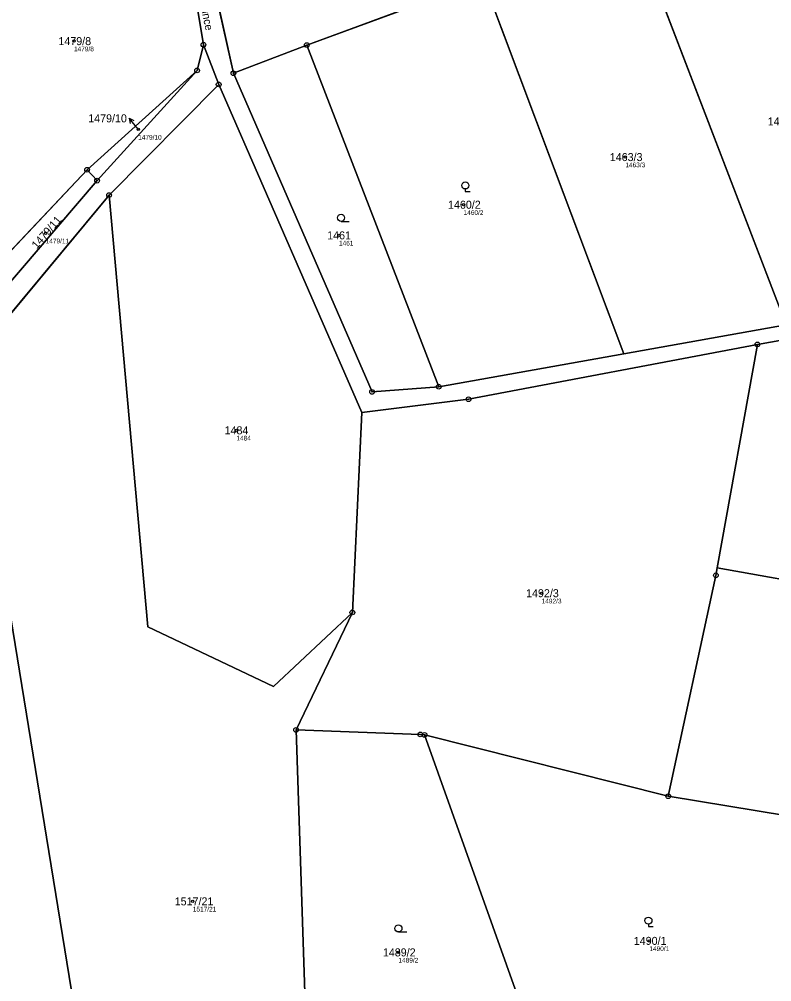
# Model space of a CAD drawing. Extents: x -751550 to -746116, y -1055108 to -1050700.
# Drawn here: x -749262.5 to -749102.6, y -1054841.3 to -1054636.8 of the extents above; entities that cross this region are included whole.
import ezdxf

# ---------------------------------------------------------------- set-up
doc = ezdxf.new("R2010")
doc.units = 0
for name, color, linetype in [('Definiční body', 7, 'Continuous'), ('Hranice parcel', 7, 'Continuous'), ('Parcelní čísla', 7, 'Continuous'), ('Polygon parcely', 7, 'Continuous'), ('Pop  PČ popisy', 7, 'Continuous'), ('Značky bodu BP', 7, 'Continuous'), ('Značky kultur', 7, 'Continuous')]:
    doc.layers.add(name, color=color, linetype=linetype)

msp = doc.modelspace()

# ---------------------------------------------------------------- linework, layer by layer
at = {"layer": 'Definiční body'}
for centre in [(-749250.88, -1054641.46), (-749237.23, -1054660.23), (-749133.7, -1054666.09), (-749168.08, -1054676.21), (-749256.9, -1054682.26), (-749194.56, -1054682.72), (-749216.36, -1054724.13), (-749151.49, -1054758.73), (-749225.63, -1054824.18), (-749128.6, -1054832.57), (-749181.93, -1054835.02)]:
    msp.add_circle(centre, 0.25, dxfattribs=at)
at = {"layer": 'Hranice parcel'}
for p, q in [((-749099.5, -1054701.75), (-749132.12, -1054616.78)), ((-749217, -1054648.29), (-749221.81, -1054626.49)), ((-749163.88, -1054628.48), (-749201.41, -1054642.3)), ((-749134.02, -1054707.89), (-749163.88, -1054628.48)), ((-749223.36, -1054642.22), (-749224.72, -1054647.7)), ((-749220.13, -1054650.67), (-749223.36, -1054642.22)), ((-749201.41, -1054642.3), (-749217, -1054648.29)), ((-749201.41, -1054642.3), (-749173.36, -1054714.89)), ((-749248.08, -1054668.77), (-749224.72, -1054647.7)), ((-749224.72, -1054647.7), (-749245.96, -1054671.1)), ((-749243.42, -1054674.15), (-749220.13, -1054650.67)), ((-749220.13, -1054650.67), (-749189.71, -1054720.33)), ((-749248.08, -1054668.77), (-749268.85, -1054690.77)), ((-749245.96, -1054671.1), (-749248.08, -1054668.77)), ((-749266.39, -1054694.97), (-749245.96, -1054671.1)), ((-749271.75, -1054708.21), (-749243.42, -1054674.15)), ((-749134.02, -1054707.89), (-749099.5, -1054701.75)), ((-749114.17, -1054753.36), (-749105.62, -1054705.87)), ((-749173.36, -1054714.89), (-749134.02, -1054707.89)), ((-749189.71, -1054720.33), (-749191.72, -1054762.81)), ((-749191.72, -1054762.81), (-749203.69, -1054787.76)), ((-749203.69, -1054787.76), (-749201.19, -1054862.86)), ((-749147.34, -1054870.21), (-749176.38, -1054788.81)), ((-749124.6, -1054801.85), (-749176.38, -1054788.81)), ((-749099.27, -1054805.99), (-749124.6, -1054801.85))]:
    msp.add_line(p, q, dxfattribs=at)
for points in [[(-749223.36, -1054642.22), (-749225.67, -1054628.07), (-749237.29, -1054590.37), (-749238.67, -1054580.27)], [(-749217, -1054648.29), (-749187.54, -1054715.98), (-749173.36, -1054714.89)], [(-749191.72, -1054762.81), (-749208.49, -1054778.55), (-749235.21, -1054765.84), (-749243.42, -1054674.15)], [(-749078.57, -1054700.84), (-749088.73, -1054757.9), (-749114.17, -1054753.36)], [(-749078.57, -1054700.84), (-749081.12, -1054701.53), (-749105.62, -1054705.87)], [(-749105.62, -1054705.87), (-749167.02, -1054717.52), (-749189.71, -1054720.33)], [(-749231.96, -1054961.55), (-749235.61, -1054940.24), (-749265.82, -1054754.82), (-749271.75, -1054708.21)], [(-749114.17, -1054753.36), (-749114.46, -1054754.93), (-749124.6, -1054801.85)], [(-749176.38, -1054788.81), (-749177.29, -1054788.71), (-749203.69, -1054787.76)]]:
    msp.add_lwpolyline(points, dxfattribs=at)
at = {"layer": 'Polygon parcely'}
for points in [[(-749106.12, -1054576.37), (-749221.81, -1054626.49), (-749217, -1054648.29), (-749201.41, -1054642.3), (-749163.88, -1054628.48), (-749132.12, -1054616.78), (-749125.24, -1054614.25), (-749102.8, -1054606.42)], [(-749224.72, -1054647.7), (-749223.36, -1054642.22), (-749225.67, -1054628.07), (-749237.29, -1054590.37), (-749238.67, -1054580.27), (-749271.66, -1054630.97), (-749288.04, -1054658.17), (-749278.52, -1054674.25), (-749268.85, -1054690.77), (-749248.08, -1054668.77)], [(-749100.4, -1054605.6), (-749102.8, -1054606.42), (-749125.24, -1054614.25), (-749132.12, -1054616.78), (-749099.5, -1054701.75), (-749081.77, -1054698.59), (-749067.82, -1054694.8)], [(-749099.5, -1054701.75), (-749132.12, -1054616.78), (-749163.88, -1054628.48), (-749134.02, -1054707.89)], [(-749173.36, -1054714.89), (-749134.02, -1054707.89), (-749163.88, -1054628.48), (-749201.41, -1054642.3)], [(-749201.41, -1054642.3), (-749217, -1054648.29), (-749187.54, -1054715.98), (-749173.36, -1054714.89)], [(-749248.08, -1054668.77), (-749245.96, -1054671.1), (-749224.72, -1054647.7)], [(-749220.13, -1054650.67), (-749243.42, -1054674.15), (-749235.21, -1054765.84), (-749208.49, -1054778.55), (-749191.72, -1054762.81), (-749189.71, -1054720.33)], [(-749248.08, -1054668.77), (-749268.85, -1054690.77), (-749266.39, -1054694.97), (-749245.96, -1054671.1)], [(-749231.96, -1054961.55), (-749205.59, -1054950.5), (-749200.41, -1054946.06), (-749200.11, -1054941.77), (-749200, -1054940.27), (-749198.56, -1054939.4), (-749199.43, -1054914.75), (-749199.93, -1054900.6), (-749200.02, -1054897.94), (-749201.19, -1054862.86), (-749203.69, -1054787.76), (-749191.72, -1054762.81), (-749208.49, -1054778.55), (-749235.21, -1054765.84), (-749243.42, -1054674.15), (-749271.75, -1054708.21), (-749265.82, -1054754.82), (-749235.61, -1054940.24)], [(-749088.73, -1054757.9), (-749114.17, -1054753.36), (-749114.46, -1054754.93), (-749124.6, -1054801.85), (-749099.27, -1054805.99), (-749061.12, -1054809.36), (-749041.33, -1054765.13), (-749034.48, -1054742.09), (-749031.21, -1054724.33), (-749028.58, -1054702.31), (-749026.88, -1054677.05), (-749035.13, -1054685.74), (-749050.06, -1054693.14), (-749078.57, -1054700.84)], [(-749078.57, -1054700.84), (-749081.12, -1054701.53), (-749105.62, -1054705.87), (-749114.17, -1054753.36), (-749088.73, -1054757.9)], [(-749167.02, -1054717.52), (-749189.71, -1054720.33), (-749191.72, -1054762.81), (-749203.69, -1054787.76), (-749177.29, -1054788.71), (-749176.38, -1054788.81), (-749124.6, -1054801.85), (-749114.46, -1054754.93), (-749114.17, -1054753.36), (-749105.62, -1054705.87)], [(-749231.09, -1055030.14), (-749229.04, -1055029.57), (-749228.67, -1055030.9), (-749223.27, -1055029.51), (-749220.25, -1055029.63), (-749220.65, -1055027.12), (-749225.44, -1054999.67), (-749231.96, -1054961.55), (-749235.61, -1054940.24), (-749265.82, -1054754.82), (-749271.75, -1054708.21), (-749291.2, -1054720.78), (-749316.97, -1054728.36), (-749323.11, -1054829.31), (-749280.79, -1054962.12), (-749256.6, -1055037.55), (-749254.56, -1055037.58), (-749230.73, -1055031.43)], [(-749143.01, -1054903.27), (-749136.95, -1054899.33), (-749137.45, -1054897.92), (-749147.34, -1054870.21), (-749176.38, -1054788.81), (-749177.29, -1054788.71), (-749203.69, -1054787.76), (-749201.19, -1054862.86), (-749177.86, -1054860.98), (-749158.66, -1054859.44)], [(-749106.18, -1054875.56), (-749088.43, -1054862.87), (-749099.27, -1054805.99), (-749124.6, -1054801.85), (-749176.38, -1054788.81), (-749147.34, -1054870.21), (-749136.29, -1054862.17), (-749121.44, -1054851.51)]]:
    msp.add_lwpolyline(points, close=True, dxfattribs=at)
for points in [[(-749099.5, -1054701.75), (-749134.02, -1054707.89), (-749173.36, -1054714.89), (-749187.54, -1054715.98), (-749217, -1054648.29), (-749221.81, -1054626.49)], [(-749225.67, -1054628.07), (-749223.36, -1054642.22), (-749220.13, -1054650.67), (-749189.71, -1054720.33), (-749167.02, -1054717.52), (-749105.62, -1054705.87), (-749081.12, -1054701.53)], [(-749271.75, -1054708.21), (-749243.42, -1054674.15), (-749220.13, -1054650.67), (-749223.36, -1054642.22), (-749224.72, -1054647.7), (-749245.96, -1054671.1), (-749266.39, -1054694.97)]]:
    msp.add_lwpolyline(points, dxfattribs=at)
at = {"layer": 'Pop  PČ popisy'}
for p, q in [((-749237.27, -1054660.18), (-749239.16, -1054657.85)), ((-749239.16, -1054657.85), (-749238.14, -1054658.31)), ((-749239.16, -1054657.85), (-749238.92, -1054658.94)), ((-749237.23, -1054660.23), (-749237.27, -1054660.18))]:
    msp.add_line(p, q, dxfattribs=at)
at = {"layer": 'Značky bodu BP'}
for centre, radius in [((-749223.36, -1054642.22), 0.5), ((-749223.36, -1054642.22), 0.0303), ((-749201.41, -1054642.3), 0.5), ((-749201.41, -1054642.3), 0.0303), ((-749224.72, -1054647.7), 0.5), ((-749224.72, -1054647.7), 0.0303), ((-749217, -1054648.29), 0.5), ((-749217, -1054648.29), 0.0303), ((-749220.13, -1054650.67), 0.5), ((-749220.13, -1054650.67), 0.0303), ((-749248.08, -1054668.77), 0.5), ((-749248.08, -1054668.77), 0.0303), ((-749245.96, -1054671.1), 0.5), ((-749245.96, -1054671.1), 0.0303), ((-749243.42, -1054674.15), 0.5), ((-749243.42, -1054674.15), 0.0303), ((-749105.62, -1054705.87), 0.5), ((-749105.62, -1054705.87), 0.0303), ((-749173.36, -1054714.89), 0.5), ((-749187.54, -1054715.98), 0.5), ((-749187.54, -1054715.98), 0.0303), ((-749173.36, -1054714.89), 0.0303), ((-749167.02, -1054717.52), 0.5), ((-749167.02, -1054717.52), 0.0303), ((-749114.46, -1054754.93), 0.5), ((-749114.46, -1054754.93), 0.0303), ((-749191.72, -1054762.81), 0.5), ((-749191.72, -1054762.81), 0.0303), ((-749203.69, -1054787.76), 0.5), ((-749203.69, -1054787.76), 0.0303), ((-749177.29, -1054788.71), 0.5), ((-749177.29, -1054788.71), 0.0303), ((-749176.38, -1054788.81), 0.5), ((-749176.38, -1054788.81), 0.0303), ((-749124.6, -1054801.85), 0.5), ((-749124.6, -1054801.85), 0.0303)]:
    msp.add_circle(centre, radius, dxfattribs=at)
at = {"layer": 'Značky kultur'}
for p, q in [((-749167.71, -1054672.87), (-749167.71, -1054673.37)), ((-749167.71, -1054673.37), (-749166.71, -1054673.37)), ((-749194.12, -1054679.74), (-749192.37, -1054679.74)), ((-749128.8, -1054829.02), (-749128.8, -1054829.52)), ((-749181.92, -1054830.68), (-749180.17, -1054830.68)), ((-749128.8, -1054829.52), (-749127.8, -1054829.52))]:
    msp.add_line(p, q, dxfattribs=at)
for centre in [(-749167.71, -1054672.12), (-749194.12, -1054678.99), (-749128.8, -1054828.27), (-749181.92, -1054829.93)]:
    msp.add_circle(centre, 0.75, dxfattribs=at)

# ---------------------------------------------------------------- texts
at = {"layer": 'Definiční body'}
for s, p in [('1479/8', (-749250.88, -1054643.62)), ('1479/10', (-749237.23, -1054662.39)), ('1463/3', (-749133.7, -1054668.25)), ('1460/2', (-749168.08, -1054678.37)), ('1479/11', (-749256.9, -1054684.42)), ('1461', (-749194.56, -1054684.88)), ('1484', (-749216.36, -1054726.29)), ('1492/3', (-749151.49, -1054760.89)), ('1517/21', (-749225.63, -1054826.34)), ('1490/1', (-749128.6, -1054834.73)), ('1489/2', (-749181.93, -1054837.18))]:
    msp.add_text(s, height=1, dxfattribs=at).set_placement(p)
at = {"layer": 'Parcelní čísla'}
for s, p in [('1479/8', (-749254.19, -1054642.31)), ('1479/10', (-749247.85, -1054658.71)), ('1463/4', (-749103.45, -1054659.37)), ('1463/3', (-749137.01, -1054666.94)), ('1460/2', (-749171.39, -1054677.06)), ('1461', (-749197.07, -1054683.57)), ('1484', (-749218.87, -1054724.98)), ('1492/3', (-749154.8, -1054759.58)), ('1517/21', (-749229.47, -1054825.03)), ('1490/1', (-749131.91, -1054833.42)), ('1489/2', (-749185.23, -1054835.87))]:
    msp.add_text(s, height=1.7, dxfattribs=at).set_placement(p)
msp.add_text('1479/11', height=1.7, rotation=49, dxfattribs=at).set_placement((-749258.78, -1054685.71))
at = {"layer": 'Pop  PČ popisy'}
msp.add_text('K Berounce', height=1.7, rotation=281, dxfattribs=at).set_placement((-749225.19, -1054627.64))

doc.saveas('drawing.dxf')
